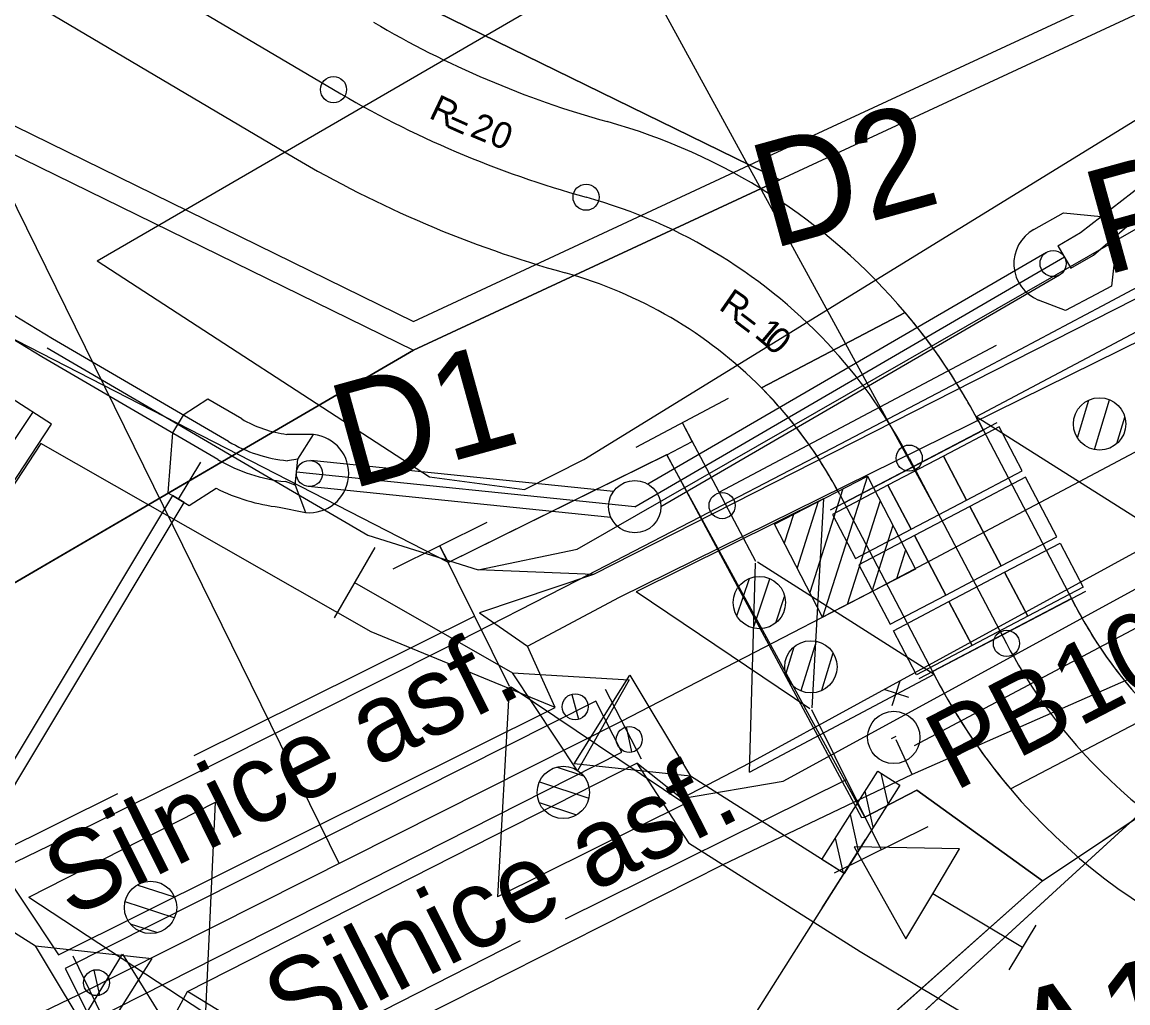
# Model space of a CAD drawing. Extents: x -9100 to -8660, y -10901 to -10569.
# Drawn here: x -8980.1 to -8958.96, y -10794.39 to -10775.64 of the extents above; entities that cross this region are included whole.
import ezdxf

# ---------------------------------------------------------------- set-up
doc = ezdxf.new("R2010")
doc.units = 0
for name, color, linetype in [('16_SSZT', 7, 'Continuous'), ('16_SSZT - DK', 7, 'Continuous'), ('17_ČD - telematika', 7, 'Continuous'), ('C3D-TRASA', 7, 'Continuous'), ('C3D-TRASA-POPIS', 7, 'Continuous'), ('Default', 7, 'Continuous'), ('HranDP', 7, 'Continuous'), ('Hranice parcel', 7, 'Continuous'), ('JC - SITU (Šraf) PK - Silnice', 7, 'Continuous'), ('JC - SITU - Přejezd', 7, 'Continuous'), ('JC - SITU - Silnice', 7, 'Continuous'), ('JC - SITU - Silnice (Slabá)', 7, 'Continuous'), ('JC - SITU - Silnice - Přerušovaná (_ _ _)', 7, 'Continuous'), ('JC - SITU - Trativody', 7, 'Continuous'), ('JC - SITU - Vpusti', 7, 'Continuous'), ('PS110241_Sdělovací zařízení', 7, 'Continuous'), ('SDĚL__BUBLINY', 7, 'Continuous'), ('Vnitřní kresba', 7, 'Continuous'), ('Vrstva 1', 7, 'Continuous'), ('Vrstva 2', 7, 'Continuous'), ('Vrstva 27', 7, 'Continuous'), ('Vrstva 3', 7, 'Continuous'), ('Vrstva 4', 7, 'Continuous'), ('Vrstva 43', 7, 'Continuous'), ('Vrstva 49', 7, 'Continuous'), ('Vrstva 51', 7, 'Continuous')]:
    doc.layers.add(name, color=color, linetype=linetype)

# ---------------------------------------------------------------- blocks, each defined once
blk = doc.blocks.new('AeccTickCircle')
at = {"layer": 'Default'}
blk.add_circle((0, 0), 5, dxfattribs=at)
blk = doc.blocks.new('AeccTickCircle_1')
at = {"layer": 'Default'}
blk.add_circle((0, 0), 5, dxfattribs=at)

msp = doc.modelspace()

# ---------------------------------------------------------------- linework, layer by layer
at = {"layer": '16_SSZT'}
msp.add_line((-8960.588, -10792.058), (-8969.887, -10800.323), dxfattribs=at)
for points in [[(-9074.585, -10817.612), (-9054.624, -10814.278), (-9033.944, -10809.249), (-9016.331, -10803.227), (-8993.207, -10794.934), (-8992.236, -10796.991), (-8989.816, -10802.65), (-8978.528, -10800.389), (-8972.071, -10800.763), (-8969.887, -10800.323), (-8960.588, -10792.058), (-8935.292, -10775.141), (-8919.684, -10767.375), (-8910.065, -10763.204), (-8903.876, -10759.887), (-8899.774, -10757.335), (-8892.343, -10752.193), (-8875.762, -10743.528)], [(-8898.973, -10756.95), (-8902.242, -10756.235), (-8903.938, -10756.596), (-8906.578, -10758.251), (-8908.097, -10761.436), (-8909.812, -10763.554), (-8921.931, -10769.83), (-8933.078, -10775.478), (-8951.398, -10784.881), (-8963.08, -10790.024), (-8966.715, -10791.759), (-8974.833, -10795.863), (-8979.944, -10798.857)], [(-8963.08, -10790.024), (-8963.391, -10789.36)]]:
    msp.add_lwpolyline(points, dxfattribs=at)
at = {"layer": '16_SSZT - DK'}
msp.add_lwpolyline([(-8978.528, -10800.389), (-8972.071, -10800.763), (-8969.887, -10800.323), (-8960.588, -10792.058), (-8935.292, -10775.141), (-8919.684, -10767.375), (-8910.065, -10763.204), (-8903.876, -10759.887), (-8899.774, -10757.335), (-8892.343, -10752.193), (-8875.762, -10743.528)], dxfattribs=at)
at = {"layer": '17_ČD - telematika'}
msp.add_line((-8960.588, -10792.058), (-8969.887, -10800.323), dxfattribs=at)
for points in [[(-8978.528, -10800.389), (-8972.071, -10800.763), (-8969.887, -10800.323), (-8960.588, -10792.058), (-8935.292, -10775.141), (-8919.684, -10767.375), (-8910.065, -10763.204), (-8903.876, -10759.887), (-8899.774, -10757.335), (-8892.343, -10752.193), (-8875.762, -10743.528)], [(-8973.866, -10800.284), (-8973.203, -10800.546), (-8973.06, -10800.825), (-8972.46, -10801.12), (-8969.887, -10800.323), (-8960.588, -10792.058), (-8935.292, -10775.141), (-8919.684, -10767.375), (-8910.065, -10763.204), (-8903.876, -10759.887), (-8899.774, -10757.335), (-8892.343, -10752.193), (-8879.745, -10745.609)]]:
    msp.add_lwpolyline(points, dxfattribs=at)
at = {"layer": 'C3D-TRASA'}
for p, q in [((-9032.282, -10742.537), (-8974.144, -10776.933)), ((-8961.811, -10783.28), (-8959.952, -10786.822)), ((-8963.139, -10783.977), (-8961.28, -10787.519)), ((-8964.467, -10784.675), (-8962.609, -10788.216))]:
    msp.add_line(p, q, dxfattribs=at)
for centre, radius, start, end in [((-8963.96, -10759.72), 20, 239.39, 254.467), ((-8971.994, -10788.625), 10, 42.1684, 74.467), ((-8971.994, -10788.625), 11.5, 27.6909, 40.2467), ((-8971.994, -10788.625), 10, 27.6909, 42.1798), ((-8971.994, -10788.625), 8.5, 27.6909, 44.7955), ((-8952.426, -10782.872), 8.5, 207.6909, 224.7955), ((-8952.426, -10782.872), 10, 207.6909, 222.1798), ((-8952.426, -10782.872), 11.5, 207.6909, 220.2467), ((-8952.426, -10782.872), 10, 222.1684, 269.7)]:
    msp.add_arc(centre, radius, start, end, dxfattribs=at)
at = {"layer": 'HranDP'}
for p, q in [((-8965.614, -10778.66), (-8977.199, -10772.987)), ((-8972.614, -10781.915), (-8965.614, -10778.66)), ((-8975.422, -10783.553), (-8972.614, -10781.915)), ((-8987.151, -10790.388), (-8975.422, -10783.553)), ((-8958.322, -10790.401), (-8960.171, -10792.093)), ((-8960.171, -10792.093), (-8971.031, -10802.048))]:
    msp.add_line(p, q, dxfattribs=at)
at = {"layer": 'Hranice parcel'}
for p, q in [((-8977.199, -10772.987), (-8965.614, -10778.66)), ((-8965.614, -10778.66), (-8972.614, -10781.915))]:
    msp.add_line(p, q, dxfattribs=at)
for points in [[(-8881.284, -10733.421), (-8906.791, -10746.989), (-8907.913, -10745.543), (-8912.442, -10748.102), (-8911.552, -10749.582), (-8937.178, -10765.452), (-8965.614, -10778.66)], [(-9045.036, -10740.565), (-9025.707, -10752.068), (-8990.653, -10773.077), (-8972.614, -10781.915)], [(-8972.614, -10781.915), (-8975.422, -10783.553), (-8987.151, -10790.388), (-8989.182, -10791.573)], [(-8958.322, -10790.401), (-8960.171, -10792.093), (-8971.031, -10802.048)]]:
    msp.add_lwpolyline(points, dxfattribs=at)
at = {"layer": 'JC - SITU (Šraf) PK - Silnice'}
for p, q in [((-8963.216, -10781.195), (-8965.962, -10782.636)), ((-8961.203, -10790.302), (-8958.457, -10788.861))]:
    msp.add_line(p, q, dxfattribs=at)
for points in [[(-8964.467, -10784.675), (-8964.384, -10784.834), (-8961.727, -10783.44), (-8961.811, -10783.28)], [(-8959.952, -10786.822), (-8960.036, -10786.663), (-8962.692, -10788.057), (-8962.609, -10788.216)]]:
    msp.add_lwpolyline(points, dxfattribs=at)
for centre, radius, start, end in [((-8971.994, -10788.625), 11.5, 33.1882, 40.2467), ((-8971.994, -10788.625), 11.5, 27.6909, 33.1882), ((-8971.994, -10788.625), 8.5, 35.1411, 44.7955), ((-8971.994, -10788.625), 8.5, 27.6909, 35.1411), ((-8952.426, -10782.872), 8.5, 207.6909, 215.1145), ((-8952.426, -10782.872), 8.5, 215.1145, 224.7955), ((-8952.426, -10782.872), 11.5, 207.6909, 213.1708), ((-8952.426, -10782.872), 11.5, 213.1708, 220.2467)]:
    msp.add_arc(centre, radius, start, end, dxfattribs=at)
at = {"layer": 'JC - SITU - Přejezd'}
for p, q in [((-8961.462, -10783.3), (-8964.649, -10784.973)), ((-8959.77, -10786.524), (-8962.958, -10788.196)), ((-8968.259, -10789.733), (-8968.943, -10788.398)), ((-8978.463, -10794.848), (-8979.121, -10793.5))]:
    msp.add_line(p, q, dxfattribs=at)
for points in [[(-8962.041, -10784.779), (-8960.978, -10784.221), (-8961.42, -10783.38), (-8962.482, -10783.938)], [(-8963.103, -10785.337), (-8962.041, -10784.779), (-8962.482, -10783.938), (-8963.545, -10784.495)], [(-8961.38, -10786.039), (-8960.317, -10785.481), (-8960.914, -10784.343), (-8961.977, -10784.901)], [(-8964.166, -10785.894), (-8963.103, -10785.337), (-8963.545, -10784.495), (-8964.607, -10785.053)], [(-8962.442, -10786.596), (-8961.38, -10786.039), (-8961.977, -10784.901), (-8963.04, -10785.458)], [(-8963.505, -10787.154), (-8962.442, -10786.596), (-8963.04, -10785.458), (-8964.102, -10786.016)], [(-8961.316, -10786.16), (-8960.253, -10785.603), (-8959.812, -10786.444), (-8960.874, -10787.001)], [(-8962.379, -10786.718), (-8961.316, -10786.16), (-8960.874, -10787.001), (-8961.937, -10787.559)], [(-8963.441, -10787.276), (-8962.379, -10786.718), (-8961.937, -10787.559), (-8963, -10788.117)]]:
    msp.add_lwpolyline(points, close=True, dxfattribs=at)
at = {"layer": 'JC - SITU - Silnice'}
for p, q in [((-9033.045, -10743.828), (-8974.908, -10778.224)), ((-8959.866, -10779.665), (-8958.292, -10778.443)), ((-8959.614, -10780.097), (-8958.103, -10778.796)), ((-8960.298, -10779.916), (-8959.866, -10779.665)), ((-8960.298, -10779.916), (-8960.047, -10780.349)), ((-8960.047, -10780.349), (-8959.614, -10780.097)), ((-8974.827, -10783.997), (-8975.024, -10784.027)), ((-8974.878, -10784.495), (-8974.827, -10783.997)), ((-8974.878, -10784.495), (-8975.065, -10784.425))]:
    msp.add_line(p, q, dxfattribs=at)
for points in [[(-8976.151, -10783.66), (-8979.515, -10781.697), (-8981.72, -10780.361)], [(-8976.353, -10784.006), (-8979.719, -10782.041), (-8981.927, -10780.703)]]:
    msp.add_lwpolyline(points, dxfattribs=at)
for centre, radius, start, end in [((-8963.96, -10759.72), 18.5, 239.39, 254.467), ((-8971.994, -10788.625), 11.5, 40.2467, 74.467), ((-8963.96, -10759.72), 21.5, 239.39, 254.467), ((-8971.994, -10788.625), 8.5, 44.7955, 74.467), ((-8974.74, -10781.242), 2.8, 239.7372, 264.1719), ((-8974.74, -10781.242), 3.2, 239.7372, 264.1719), ((-8952.426, -10782.872), 11.5, 220.2467, 269.7)]:
    msp.add_arc(centre, radius, start, end, dxfattribs=at)
at = {"layer": 'JC - SITU - Silnice (Slabá)'}
for p, q in [((-8975.899, -10783.228), (-8976.544, -10782.852)), ((-8974.527, -10783.525), (-8975.034, -10783.523)), ((-8974.827, -10783.997), (-8974.527, -10783.525)), ((-8974.878, -10784.495), (-8974.68, -10785.017)), ((-8975.181, -10784.915), (-8974.68, -10785.017))]:
    msp.add_line(p, q, dxfattribs=at)
for points in [[(-8960.757, -10779.605), (-8960.192, -10779.286), (-8959.471, -10779.358), (-8959.166, -10779.712), (-8959.27, -10780.689), (-8959.573, -10780.85), (-8960.154, -10781.158), (-8960.665, -10780.955)], [(-8976.544, -10782.852), (-8977.017, -10783.155), (-8977.223, -10783.497), (-8977.309, -10784.639), (-8977.219, -10784.694), (-8976.996, -10784.828), (-8976.906, -10784.882), (-8976.388, -10784.554)]]:
    msp.add_lwpolyline(points, dxfattribs=at)
for centre, radius, start, end in [((-8960.388, -10780.258), 0.75, 119.4762, 248.3275), ((-8974.74, -10781.242), 2.3, 239.7372, 262.6626), ((-8974.604, -10784.271), 0.75, 264.1719, 84.1719), ((-8974.74, -10781.242), 3.7, 243.5514, 263.1509)]:
    msp.add_arc(centre, radius, start, end, dxfattribs=at)
at = {"layer": 'JC - SITU - Silnice - Přerušovaná (_ _ _)'}
for p, q in [((-8965.962, -10782.636), (-8963.216, -10781.195)), ((-8961.203, -10790.302), (-8958.457, -10788.861))]:
    msp.add_line(p, q, dxfattribs=at)
at = {"layer": 'JC - SITU - Trativody'}
msp.add_lwpolyline([(-8957.015, -10779.77), (-8959.456, -10781.071), (-8961.957, -10782.395), (-8964.462, -10783.711), (-8966.715, -10784.885), (-8966.97, -10785.018), (-8969.483, -10786.314), (-8972, -10787.601), (-8974.522, -10788.875), (-8977.049, -10790.138), (-8979.581, -10791.387), (-8982.12, -10792.622), (-8984.521, -10793.774)], dxfattribs=at)
msp.add_circle((-8966.715, -10784.885), 0.25, dxfattribs=at)
at = {"layer": 'JC - SITU - Vpusti'}
for p, q in [((-8968.386, -10784.906), (-8960.172, -10780.132)), ((-8968.137, -10784.472), (-8960.514, -10780.042)), ((-8967.886, -10784.904), (-8960.263, -10780.474)), ((-8977.108, -10784.761), (-8976.683, -10784.054)), ((-8968.791, -10784.613), (-8974.578, -10784.023)), ((-8968.386, -10784.906), (-8974.852, -10784.246)), ((-8968.842, -10785.111), (-8974.629, -10784.52))]:
    msp.add_line(p, q, dxfattribs=at)
msp.add_lwpolyline([(-8981.284, -10791.958), (-8976.996, -10784.828), (-8977.219, -10784.694), (-8981.507, -10791.824)], close=True, dxfattribs=at)
for centre, radius in [((-8960.388, -10780.258), 0.25), ((-8974.604, -10784.271), 0.25), ((-8968.386, -10784.906), 0.5)]:
    msp.add_circle(centre, radius, dxfattribs=at)
at = {"layer": 'PS110241_Sdělovací zařízení'}
msp.add_lwpolyline([(-8978.049, -10801.771), (-8978.528, -10800.389), (-8972.071, -10800.763), (-8969.887, -10800.323), (-8960.588, -10792.058), (-8962.993, -10790.328), (-8963.989, -10790.84), (-8967.772, -10783.915), (-8971.948, -10785.974), (-8985.392, -10779.074)], dxfattribs=at)
at = {"layer": 'SDĚL__BUBLINY'}
msp.add_line((-8977.036, -10758.584), (-8962.572, -10785.058), dxfattribs=at)
at = {"layer": 'Vnitřní kresba'}
for p, q in [((-8965.828, -10778.207), (-8937.414, -10765.015)), ((-8990.419, -10772.635), (-8972.613, -10781.364)), ((-8972.613, -10781.364), (-8965.828, -10778.207))]:
    msp.add_line(p, q, dxfattribs=at)
at = {"layer": 'Vrstva 1'}
for p, q in [((-8967.772, -10783.915), (-8964.049, -10790.849)), ((-8960.588, -10792.058), (-8956.365, -10789.234)), ((-8964.049, -10790.849), (-8963.989, -10790.84)), ((-8963.989, -10790.84), (-8963.675, -10791.468)), ((-8960.588, -10792.058), (-8969.887, -10800.323))]:
    msp.add_line(p, q, dxfattribs=at)
for points in [[(-9071.078, -10824.031), (-9068.55, -10823.67), (-9059.39, -10822.051), (-9049.732, -10820.012), (-9040.576, -10817.765), (-9031.032, -10815.085), (-9021.565, -10812.071), (-9019.212, -10811.266), (-9010.687, -10808.158), (-9001.881, -10804.632), (-8992.751, -10800.668), (-8983.884, -10796.567), (-8979.025, -10794.235), (-8968.639, -10789.006), (-8963.908, -10786.557), (-8955.013, -10781.841), (-8946.607, -10777.298), (-8938.34, -10772.786), (-8931.689, -10769.156), (-8930.764, -10768.65), (-8923.574, -10764.727), (-8915.206, -10760.16)], [(-8967.772, -10783.915), (-8967.291, -10783.658), (-8967.475, -10783.302)], [(-8967.776, -10783.913), (-8971.948, -10785.974), (-8972.111, -10785.655)], [(-8963.989, -10790.84), (-8962.993, -10790.328), (-8960.588, -10792.058)]]:
    msp.add_lwpolyline(points, dxfattribs=at)
at = {"layer": 'Vrstva 2'}
for p, q in [((-8958.324, -10781.309), (-8961.857, -10783.185)), ((-8966.772, -10784.628), (-8961.471, -10781.816)), ((-8968.358, -10783.771), (-8966.591, -10782.834)), ((-8959.923, -10783.587), (-8959.703, -10782.869)), ((-8959.599, -10783.811), (-8959.309, -10782.864)), ((-8966.069, -10785.953), (-8967.475, -10783.302)), ((-8958.481, -10785.328), (-8961.857, -10783.185)), ((-8959.173, -10783.7), (-8959.019, -10783.197)), ((-8964.775, -10784.757), (-8968.357, -10786.536)), ((-8964.775, -10784.757), (-8965.003, -10788.75)), ((-8971.216, -10785.21), (-8973.007, -10786.1)), ((-8970.777, -10788.342), (-8972.111, -10785.655)), ((-8966.195, -10789.982), (-8966.075, -10785.984)), ((-8966.038, -10785.962), (-8962.662, -10788.107)), ((-8966.434, -10786.991), (-8966.195, -10786.279)), ((-8966.117, -10787.223), (-8965.801, -10786.285)), ((-8965.04, -10788.771), (-8968.357, -10786.536)), ((-8965.688, -10787.124), (-8965.52, -10786.625)), ((-8957.746, -10786.663), (-8963.046, -10789.476)), ((-8971.444, -10786.999), (-8976.817, -10789.668)), ((-8964.92, -10787.48), (-8965.21, -10788.427)), ((-8965.346, -10787.591), (-8965.5, -10788.094)), ((-8964.596, -10787.704), (-8964.817, -10788.422)), ((-8966.195, -10789.982), (-8962.662, -10788.107)), ((-8970.787, -10788.373), (-8971.011, -10792.366)), ((-8967.428, -10790.587), (-8970.748, -10788.354)), ((-8965.009, -10788.781), (-8963.675, -10791.468)), ((-8969.866, -10789.884), (-8969.368, -10790.052)), ((-8970.204, -10790.166), (-8969.266, -10790.481)), ((-8964.342, -10790.125), (-8969.716, -10792.793)), ((-8983.643, -10793.057), (-8978.269, -10790.388)), ((-8979.967, -10792.369), (-8976.401, -10790.556)), ((-8976.588, -10794.551), (-8976.401, -10790.556)), ((-8967.428, -10790.587), (-8971.011, -10792.366)), ((-8970.211, -10790.559), (-8969.499, -10790.798)), ((-8962.78, -10791.023), (-8964.571, -10791.913)), ((-8977.184, -10792.371), (-8977.898, -10792.138)), ((-8979.967, -10792.369), (-8976.626, -10794.57)), ((-8977.187, -10792.764), (-8978.128, -10792.457)), ((-8977.522, -10793.049), (-8978.022, -10792.886)), ((-8975.918, -10795.919), (-8970.569, -10793.2))]:
    msp.add_line(p, q, dxfattribs=at)
for centre in [(-8959.5, -10783.324), (-8966.004, -10786.739), (-8965.019, -10787.967), (-8969.751, -10790.368), (-8977.642, -10792.566)]:
    msp.add_circle(centre, 0.5, dxfattribs=at)
at = {"layer": 'Vrstva 27'}
msp.add_line((-8963.479, -10789.34), (-8963.39, -10789.294), dxfattribs=at)
msp.add_circle((-8963.434, -10789.317), 0.5, dxfattribs=at)
at = {"layer": 'Vrstva 3'}
for p, q in [((-8963.939, -10784.321), (-8964.796, -10787.017)), ((-8964.41, -10784.565), (-8965.039, -10786.546)), ((-8964.881, -10784.809), (-8965.283, -10786.074)), ((-8963.695, -10784.792), (-8964.325, -10786.773)), ((-8965.352, -10785.052), (-8965.527, -10785.604)), ((-8963.451, -10785.263), (-8963.853, -10786.529)), ((-8963.208, -10785.734), (-8963.383, -10786.285))]:
    msp.add_line(p, q, dxfattribs=at)
msp.add_lwpolyline([(-8963.019, -10786.097), (-8964.796, -10787.017), (-8965.715, -10785.241), (-8963.939, -10784.321)], close=True, dxfattribs=at)
at = {"layer": 'Vrstva 4'}
for p, q in [((-8974.037, -10791.724), (-8991.814, -10755.583)), ((-8973.356, -10785.683), (-8974.131, -10787.032)), ((-8969.586, -10788.494), (-8969.46, -10788.967)), ((-8968.439, -10789.594), (-8968.543, -10789.115)), ((-8967.491, -10790.487), (-8968.343, -10789.807)), ((-8963.542, -10790.586), (-8963.673, -10790.002)), ((-8963.825, -10791.034), (-8963.981, -10790.344)), ((-8964.109, -10791.483), (-8964.264, -10790.793)), ((-8964.803, -10792.575), (-8963.966, -10791.263)), ((-8964.396, -10791.911), (-8964.547, -10791.241)), ((-8967.056, -10796.145), (-8964.384, -10791.919)), ((-8978.724, -10793.767), (-8978.62, -10794.245))]:
    msp.add_line(p, q, dxfattribs=at)
for points in [[(-8878.837, -10737.9), (-8884.05, -10740.755), (-8907.714, -10753.704), (-8929.956, -10766.035), (-8953.482, -10778.221), (-8969.174, -10786.201), (-8971.356, -10786.933), (-8970.433, -10787.575), (-8968.68, -10786.636), (-8952.884, -10778.842), (-8929.737, -10766.245), (-8907.522, -10754.16), (-8883.768, -10741.075), (-8878.641, -10738.258)], [(-8877.029, -10741.209), (-8882.153, -10744.006), (-8905.333, -10756.826), (-8927.898, -10769.268), (-8951.338, -10781.689), (-8966.191, -10789.81), (-8967.491, -10790.487)], [(-8967.491, -10790.487), (-8965.547, -10790.154), (-8951.016, -10782.224), (-8927.695, -10769.647), (-8905.236, -10757.41), (-8902.231, -10755.792), (-8881.893, -10744.368), (-8876.806, -10741.618)], [(-8973.743, -10786.358), (-8970.723, -10788.081), (-8968.492, -10788.218), (-8969.477, -10789.956), (-8970.723, -10788.081)], [(-8983.981, -10793.19), (-8984.367, -10790.681), (-8983.628, -10789.626), (-8980.756, -10791.441), (-8979.402, -10793.471), (-8969.905, -10788.745), (-8970.433, -10787.575)], [(-8964.384, -10791.919), (-8967.322, -10790.059), (-8969.545, -10789.819), (-8968.481, -10788.128), (-8967.322, -10790.059)], [(-8969.132, -10788.626), (-8979.273, -10793.733), (-8978.768, -10794.734), (-8968.631, -10789.599), (-8969.132, -10788.626)], [(-8977.943, -10796.031), (-8976.938, -10794.174), (-8968.343, -10789.807)], [(-8982.779, -10791.441), (-8979.841, -10793.302), (-8977.619, -10793.541), (-8978.683, -10795.232), (-8979.841, -10793.302)], [(-8974.026, -10797.188), (-8976.991, -10795.373), (-8979.217, -10795.166), (-8978.179, -10793.459), (-8976.991, -10795.373)]]:
    msp.add_lwpolyline(points, dxfattribs=at)
msp.add_lwpolyline([(-8964.807, -10791.652), (-8963.738, -10789.961), (-8963.316, -10790.228), (-8964.384, -10791.919)], close=True, dxfattribs=at)
for centre in [(-8969.524, -10788.73), (-8968.49, -10789.355), (-8978.673, -10794.005)]:
    msp.add_circle(centre, 0.248, dxfattribs=at)
at = {"layer": 'Vrstva 43'}
msp.add_line((-8984.778, -10790.436), (-8979.882, -10783.083), dxfattribs=at)
msp.add_lwpolyline([(-8980.305, -10782.83), (-8985.118, -10790.158), (-8984.367, -10790.681), (-8979.532, -10783.327), (-8980.305, -10782.83)], dxfattribs=at)
at = {"layer": 'Vrstva 49'}
for p, q in [((-8963.627, -10788.395), (-8963.15, -10788.546)), ((-8963.464, -10788.709), (-8963.313, -10788.232))]:
    msp.add_line(p, q, dxfattribs=at)
for points in [[(-8978.662, -10780.206), (-8958.735, -10768.644), (-8935.621, -10755.565), (-8884.993, -10726.632)], [(-8978.662, -10780.206), (-8972.308, -10784.335), (-8970.493, -10784.578), (-8969.357, -10784.006), (-8954.982, -10775.152), (-8933.011, -10762.4), (-8911.309, -10749.16), (-8911, -10749.364), (-8910.159, -10750.652), (-8909.705, -10751.264)], [(-8979.617, -10781.869), (-8973.485, -10785.447), (-8971.382, -10786.114), (-8969.484, -10785.715), (-8953.993, -10776.842), (-8931.757, -10763.714), (-8909.746, -10751.3), (-8909.705, -10751.264)], [(-8953.482, -10778.221), (-8969.174, -10786.201), (-8971.382, -10786.114)]]:
    msp.add_lwpolyline(points, dxfattribs=at)
at = {"layer": 'Vrstva 51'}
msp.add_line((-8961.228, -10793.761), (-8960.715, -10792.903), dxfattribs=at)
for points in [[(-8973.425, -10787.295), (-8979.74, -10783.699), (-8983.628, -10789.626), (-8980.756, -10791.441), (-8979.402, -10793.471), (-8969.905, -10788.745), (-8973.425, -10787.295)], [(-8948.497, -10810.867), (-8960.406, -10804.026), (-8969.567, -10798.679), (-8976.938, -10794.174), (-8968.343, -10789.807), (-8967.358, -10791.334), (-8964.078, -10793.407), (-8956.463, -10797.959), (-8944.942, -10804.675)], [(-8960.971, -10793.332), (-8962.688, -10792.306), (-8962.175, -10791.447), (-8964.19, -10791.408), (-8963.201, -10793.164), (-8962.688, -10792.306)]]:
    msp.add_lwpolyline(points, dxfattribs=at)

# ---------------------------------------------------------------- block references
at = {"layer": 'C3D-TRASA-POPIS'}
for name, p, xscale, yscale, rotation in [('AeccTickCircle_1', (-8974.144, -10776.933), 0.049999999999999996, 0.04999999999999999, -30.609987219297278), ('AeccTickCircle_1', (-8969.316, -10778.99), 0.04999999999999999, 0.049999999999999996, -15.533020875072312), ('AeccTickCircle', (-8963.139, -10783.977), 0.049999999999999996, 0.04999999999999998, -62.30913781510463), ('AeccTickCircle', (-8961.28, -10787.519), 0.049999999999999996, 0.04999999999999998, -62.30913781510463)]:
    msp.add_blockref(name, p, dxfattribs=dict(at, xscale=xscale, yscale=yscale, rotation=rotation))

# ---------------------------------------------------------------- texts
for s, rotation, p in [('R', 334.7128, (-8972.343, -10777.465)), ('2', 337.2222, (-8971.558, -10777.815)), ('=', 335.8563, (-8972.046, -10777.759)), ('0', 338.3657, (-8971.195, -10777.963)), ('R', 325.306, (-8966.8, -10781.122)), ('=', 322.8468, (-8966.569, -10781.466)), ('1', 319.9091, (-8966.117, -10781.644)), ('0', 318.5262, (-8965.951, -10781.788))]:
    msp.add_text(s, height=0.5, rotation=rotation, dxfattribs=at).set_placement(p)
at = {"layer": 'Vrstva 27'}
msp.add_text('PB10', height=1.5, rotation=27.3728, dxfattribs=at).set_placement((-8962.274, -10790.358))
at = {"layer": 'Vrstva 3'}
for s, p in [('PB10', (-8959.406, -10780.493)), ('D2', (-8965.774, -10779.984)), ('D1', (-8973.818, -10784.578)), ('A1', (-8960.862, -10796.225))]:
    msp.add_text(s, height=2, rotation=15.4127, dxfattribs=at).set_placement(p)
at = {"layer": 'Vrstva 51'}
for rotation, p in [(26.4582, (-8979.171, -10792.787)), (26.9338, (-8974.951, -10795.216))]:
    msp.add_text('Silnice asf.', height=1.5, rotation=rotation, dxfattribs=at).set_placement(p)

doc.saveas('drawing.dxf')
